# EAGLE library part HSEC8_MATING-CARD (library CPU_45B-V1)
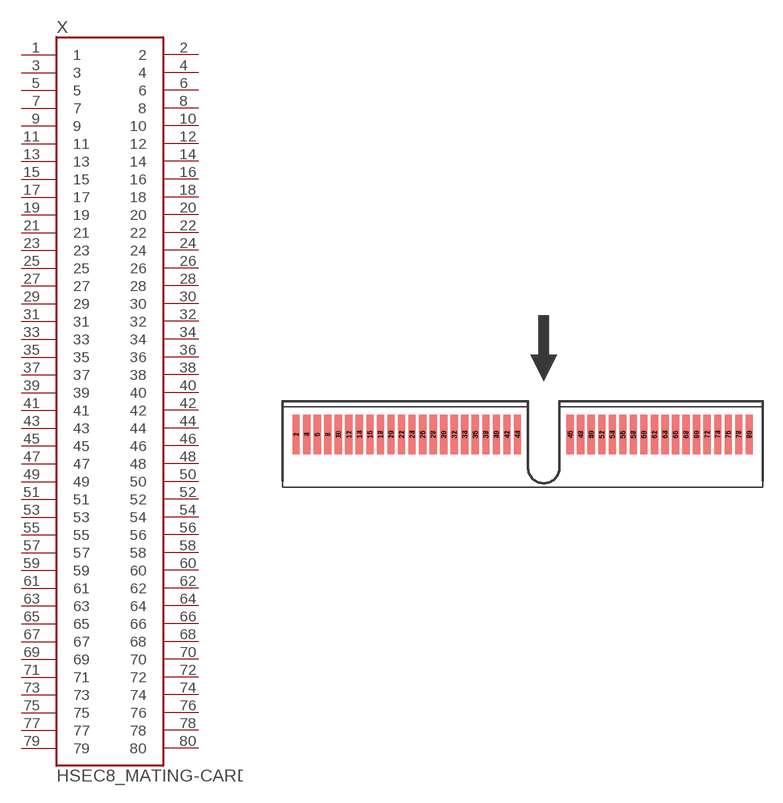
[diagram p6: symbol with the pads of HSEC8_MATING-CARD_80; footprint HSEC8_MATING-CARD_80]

Designator prefix X

## HSEC8_MATING-CARD  [HSEC8_MATING-CARD_80]
1  1
2  2
3  3
4  4
5  5
6  6
7  7
8  8
9  9
10  10
11  11
12  12
13  13
14  14
15  15
16  16
17  17
18  18
19  19
20  20
21  21
22  22
23  23
24  24
25  25
26  26
27  27
28  28
29  29
30  30
31  31
32  32
33  33
34  34
35  35
36  36
37  37
38  38
39  39
40  40
41  41
42  42
43  43
44  44
45  45
46  46
47  47
48  48
49  49
50  50
51  51
52  52
53  53
54  54
55  55
56  56
57  57
58  58
59  59
60  60
61  61
62  62
63  63
64  64
65  65
66  66
67  67
68  68
69  69
70  70
71  71
72  72
73  73
74  74
75  75
76  76
77  77
78  78
79  79
80  80

## Footprint HSEC8_MATING-CARD_80 (pad centres in mm)
This footprint has its milling outline on layer 46 (Milling)
smd 0.55 x 3 bottom: 1 -18.8,-2.5; 3 -18,-2.5; 5 -17.2,-2.5; 7 -16.4,-2.5; 9 -15.6,-2.5; 11 -14.8,-2.5; 13 -14,-2.5; 15 -13.2,-2.5; 17 -12.4,-2.5; 19 -11.6,-2.5; 21 -10.8,-2.5; 23 -10,-2.5; 25 -9.2,-2.5; 27 -8.4,-2.5; 29 -7.6,-2.5; 31 -6.8,-2.5; 33 -6,-2.5; 35 -5.2,-2.5; 37 -4.4,-2.5; 39 -3.6,-2.5; 41 -2.8,-2.5; 43 -2,-2.5; 45 2,-2.5; 47 2.8,-2.5; 49 3.6,-2.5; 51 4.4,-2.5; 53 5.2,-2.5; 55 6,-2.5; 57 6.8,-2.5; 59 7.6,-2.5; 61 8.4,-2.5; 63 9.2,-2.5; 65 10,-2.5; 67 10.8,-2.5; 69 11.6,-2.5; 71 12.4,-2.5; 73 13.2,-2.5; 75 14,-2.5; 77 14.8,-2.5; 79 15.6,-2.5
smd 0.55 x 3: 2 -18.8,-2.5; 4 -18,-2.5; 6 -17.2,-2.5; 8 -16.4,-2.5; 10 -15.6,-2.5; 12 -14.8,-2.5; 14 -14,-2.5; 16 -13.2,-2.5; 18 -12.4,-2.5; 20 -11.6,-2.5; 22 -10.8,-2.5; 24 -10,-2.5; 26 -9.2,-2.5; 28 -8.4,-2.5; 30 -7.6,-2.5; 32 -6.8,-2.5; 34 -6,-2.5; 36 -5.2,-2.5; 38 -4.4,-2.5; 40 -3.6,-2.5; 42 -2.8,-2.5; 44 -2,-2.5; 46 2,-2.5; 48 2.8,-2.5; 50 3.6,-2.5; 52 4.4,-2.5; 54 5.2,-2.5; 56 6,-2.5; 58 6.8,-2.5; 60 7.6,-2.5; 62 8.4,-2.5; 64 9.2,-2.5; 66 10,-2.5; 68 10.8,-2.5; 70 11.6,-2.5; 72 12.4,-2.5; 74 13.2,-2.5; 76 14,-2.5; 78 14.8,-2.5; 80 15.6,-2.5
